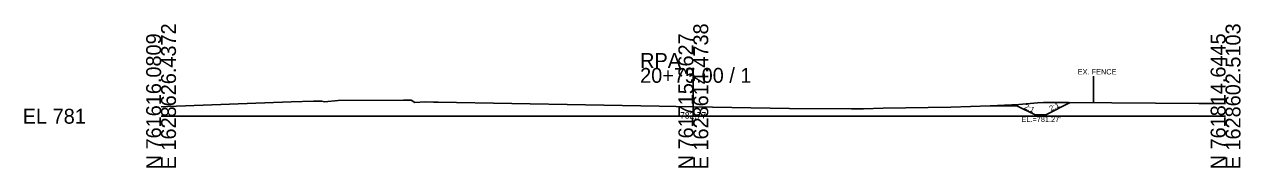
# Model space of a CAD drawing. Extents: x -26 to 203, y 990 to 7517.
# Drawn here: x -25.7 to 202.8, y 5490.3 to 5517.3 of the extents above; entities that cross this region are included whole.
import ezdxf

# ---------------------------------------------------------------- set-up
doc = ezdxf.new("R2010")
doc.units = 0
for name, color, linetype in [('Exist Cross Section Cell', 7, 'Continuous'), ('Exist XS Center Line Elevation Label', 7, 'Continuous'), ('Exist XS Ground Line', 7, 'Continuous'), ('Prop XS DDE', 7, 'Continuous'), ('Prop XS DDE Elevations', 7, 'Continuous'), ('Prop XS Side Slope Text', 7, 'Continuous')]:
    doc.layers.add(name, color=color, linetype=linetype)

msp = doc.modelspace()

# ---------------------------------------------------------------- linework, layer by layer
at = {"layer": 'Exist Cross Section Cell'}
for p, q in [((100, 5500), (100, 5509.1)), ((0, 5500), (100, 5500)), ((100, 5500), (200, 5500))]:
    msp.add_line(p, q, dxfattribs=at)
at = {"layer": 'Exist XS Ground Line'}
for p, q in [((175.16, 5502.54), (175.16, 5507.54)), ((0, 5501.8), (1.26, 5501.83)), ((1.26, 5501.83), (24.47, 5502.71)), ((24.47, 5502.71), (28.61, 5502.81)), ((28.61, 5502.81), (30.21, 5502.81)), ((30.21, 5502.81), (30.71, 5502.74)), ((30.71, 5502.74), (33.29, 5502.95)), ((33.29, 5502.95), (45.57, 5503.03)), ((45.57, 5503.03), (46.97, 5503.03)), ((46.97, 5503.03), (47.67, 5502.61)), ((47.67, 5502.61), (49.6, 5502.72)), ((49.6, 5502.72), (51.16, 5502.68)), ((51.16, 5502.68), (52.06, 5502.66)), ((52.06, 5502.66), (93.56, 5501.87)), ((93.56, 5501.87), (100, 5501.77)), ((100, 5501.77), (118.08, 5501.46)), ((118.08, 5501.46), (129.72, 5501.39)), ((129.72, 5501.39), (130.67, 5501.37)), ((130.67, 5501.37), (131.99, 5501.42)), ((131.99, 5501.42), (135.64, 5501.55)), ((135.64, 5501.55), (148.38, 5501.71)), ((148.38, 5501.71), (155.8, 5501.97)), ((155.8, 5501.97), (161.15, 5502.24)), ((161.15, 5502.24), (164.64, 5502.53)), ((164.64, 5502.53), (165.81, 5502.57)), ((165.81, 5502.57), (170.46, 5502.57)), ((170.46, 5502.57), (194.99, 5502.41)), ((194.99, 5502.41), (200, 5502.41))]:
    msp.add_line(p, q, dxfattribs=at)
at = {"layer": 'Prop XS DDE'}
for p, q in [((155.8, 5501.97), (160.8, 5501.97)), ((160.8, 5501.97), (164.21, 5500.27)), ((166.21, 5500.27), (170.8, 5502.57)), ((164.21, 5500.27), (166.21, 5500.27))]:
    msp.add_line(p, q, dxfattribs=at)

# ---------------------------------------------------------------- texts
at = {"layer": 'Exist Cross Section Cell'}
for s, p in [('E 1628626.4372', (2.8, 5490)), ('E 1628614.4738', (102.8, 5490)), ('E 1628602.5103', (202.8, 5490)), ('N 761616.0809', (0, 5490)), ('N 761715.3627', (100, 5490)), ('N 761814.6445', (200, 5490))]:
    msp.add_text(s, height=2.8, rotation=90, dxfattribs=at).set_placement(p)
for s, p in [('RPA', (90, 5509.1)), ('20+75.00 / 1', (90, 5506.3)), ('EL 781', (-26, 5498.6))]:
    msp.add_text(s, height=2.8, dxfattribs=at).set_placement(p)
at = {"layer": 'Exist XS Center Line Elevation Label'}
msp.add_text('782.77', height=1.2, dxfattribs=at).set_placement((97.52, 5499.57))
at = {"layer": 'Exist XS Ground Line'}
msp.add_text('EX. FENCE', height=1, dxfattribs=at).set_placement((172.22, 5507.87))
at = {"layer": 'Prop XS DDE Elevations'}
msp.add_text("EL.=781.27'", height=1, dxfattribs=at).set_placement((161.65, 5498.93))
at = {"layer": 'Prop XS Side Slope Text'}
for rotation, p in [(335.18, (162.09, 5501.48)), (27.5505, (167.2, 5500.94))]:
    msp.add_text('2:1', height=1, rotation=rotation, dxfattribs=at).set_placement(p)

doc.saveas('drawing.dxf')
